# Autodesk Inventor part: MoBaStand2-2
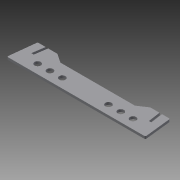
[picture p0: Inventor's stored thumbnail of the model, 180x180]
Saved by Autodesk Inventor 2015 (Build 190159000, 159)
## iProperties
Created: 2017-04
Part Number: MoBaStand2-2
Material: Generisch
Document SubType Name: Modeling
Designer: Andreas
Density: 1 g/cm^3
Appearance: Vorgabe
Author: Andreas
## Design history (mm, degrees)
sketch "Skizze1"
  geometry: L1 (2.235, 0)-(112.5, 0); L2 (4.802, 43.221)-(0.247, 2.221); L3 (6.79, 45)-(18, 45); L4 (18, 45)-(15, 24.737); L5 (15, 24.737)-(19, 24.737); L6 (22, 45)-(19, 24.737); L7 (22, 45)-(36.394, 45); L8 (51.496, 35.336)-(37.504, 44.664); L9 (112.5, 35)-(52.606, 35); L10 (220.198, 43.221)-(224.753, 2.221); L11 (218.21, 45)-(207, 45); L12 (207, 45)-(210, 24.737); L13 (210, 24.737)-(206, 24.737); L14 (203, 45)-(206, 24.737); L15 (203, 45)-(188.606, 45); L16 (173.504, 35.336)-(187.496, 44.664); L17 (112.5, 35)-(172.394, 35); L18 (222.765, 0)-(112.5, 0); A1 r 2 centre (2.235, 2) between (0.247, 2.221) and (2.235, 0); A2 r 2 centre (6.79, 43) between (6.79, 45) and (4.802, 43.221); A3 r 2 centre (36.394, 43) between (37.504, 44.664) and (36.394, 45); A4 r 2 centre (36.394, 43) between (37.504, 44.664) and (36.394, 45); A5 r 2 centre (52.606, 37) between (51.496, 35.336) and (52.606, 35); A6 r 2 centre (172.394, 37) between (172.394, 35) and (173.504, 35.336); A7 r 2 centre (188.606, 43) between (188.606, 45) and (187.496, 44.664); A8 r 2 centre (218.21, 43) between (220.198, 43.221) and (218.21, 45); A9 r 2 centre (222.765, 2) between (222.765, 0) and (224.753, 2.221); 9 further points
  constraints: 36 end point, 18 point on circle, 18 point on line, 18 tangent, 9 centre point, 8 equal radius, 4 horizontal, 1 coincident
  dimensions: "d0" = 112.5 distance of point (0, 0) L1.end; "d1" = 13 distance of point (5, 45) L3.end; "d2" = 83.6598 deg angle of L1 L2; "d5" = 4 distance of L4.end L5.end; "d6" = 4 distance of point (18, 45) L6.start; "d7" = 15 distance of L6.start point (37, 45); "d9" = 45 distance from line of L1 point (5, 45); "d15" = 2 radius of A1
extrude "Extrusion1" new body sketch "Skizze1" distance "d13" = 4; taper "d14" = 0 deg
sketch "Skizze2"
  geometry: L1 (2.235, 0)-(222.765, 0) reference; L2 (112.5, 0)-(112.5, 35); L3 (172.394, 35)-(52.606, 35) reference; C1 r 5 at (35, 15); C2 r 5 at (55, 15); C3 r 5 at (75, 15); C4 r 5 at (190, 15); C5 r 5 at (170, 15); C6 r 5 at (150, 15); 4 further points
  constraints: 6 centre point, 3 coincident, 3 symmetric about line, 2 end point, 2 midpoint, 3 other
  dimensions: "d16" = 10 diameter of C1; "d17" = 10 diameter of C2; "d18" = 10 diameter of C3
extrude "Extrusion2" cut sketch "Skizze2" distance "d19" = 4; taper "d20" = 0 deg
node "Volumenkörper1"
